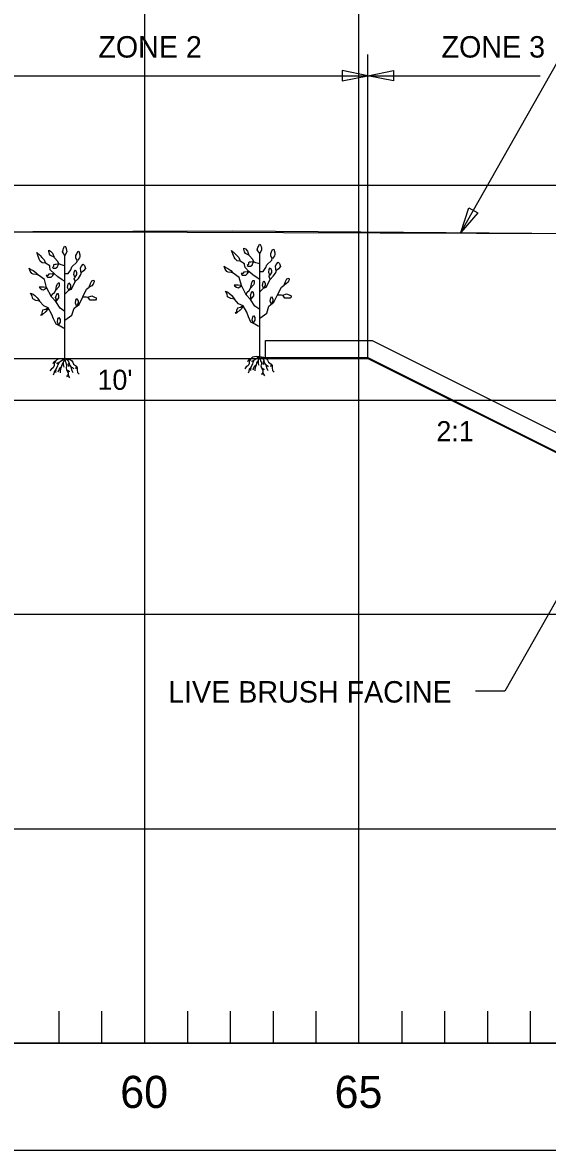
# Model space of a CAD drawing. Extents: x 1578769 to 1579225, y 724002 to 724828.
# Drawn here: x 1578861.35 to 1578873.59, y 724300.65 to 724326.95 of the extents above; entities that cross this region are included whole.
import ezdxf

# ---------------------------------------------------------------- set-up
doc = ezdxf.new("R2010")
doc.units = 0
for name, color, linetype in [('1', 7, 'Continuous'), ('Default', 7, 'Continuous'), ('Old_Level_1', 7, 'Continuous'), ('Old_Level_41', 7, 'Continuous'), ('Old_Level_42', 7, 'Continuous'), ('R_Exist Surface', 7, 'Continuous'), ('R_Fin Surface', 7, 'Continuous')]:
    doc.layers.add(name, color=color, linetype=linetype)

msp = doc.modelspace()

# ---------------------------------------------------------------- linework, layer by layer
at = {"layer": '1'}
for p, q in [((1578869.405, 724319.118), (1578869.405, 724326.205)), ((1578859.405, 724325.713), (1578869.405, 724325.713)), ((1578869.405, 724325.713), (1578873.428, 724325.713)), ((1578862.337, 724319.118), (1578862.337, 724321.518)), ((1578866.883, 724319.166), (1578866.883, 724321.566)), ((1578862.342, 724319.113), (1578862.344, 724319.117)), ((1578866.888, 724319.161), (1578866.89, 724319.165))]:
    msp.add_line(p, q, dxfattribs=at)
for points in [[(1578871.571, 724322.055), (1578874.669, 724327.519), (1578875.354, 724327.519)], [(1578862.624, 724321.405), (1578862.593, 724321.462), (1578862.593, 724321.518), (1578862.612, 724321.563), (1578862.637, 724321.613), (1578862.662, 724321.619), (1578862.688, 724321.537), (1578862.688, 724321.499), (1578862.681, 724321.468), (1578862.631, 724321.405)], [(1578867.17, 724321.452), (1578867.139, 724321.509), (1578867.139, 724321.566), (1578867.158, 724321.61), (1578867.183, 724321.661), (1578867.208, 724321.667), (1578867.233, 724321.585), (1578867.233, 724321.547), (1578867.227, 724321.516), (1578867.177, 724321.452)], [(1578862.325, 724320.925), (1578862.274, 724320.95), (1578862.173, 724321.026), (1578862.085, 724321.102), (1578861.997, 724321.19), (1578861.984, 724321.266), (1578861.984, 724321.278), (1578861.883, 724321.342)], [(1578862.337, 724321.278), (1578862.249, 724321.304), (1578862.199, 724321.329), (1578862.173, 724321.379), (1578862.098, 724321.468), (1578862.085, 724321.48)], [(1578862.337, 724321.102), (1578862.413, 724321.102), (1578862.476, 724321.19), (1578862.501, 724321.253), (1578862.615, 724321.367), (1578862.628, 724321.405)], [(1578862.716, 724321.102), (1578862.703, 724321.222), (1578862.716, 724321.266), (1578862.767, 724321.316), (1578862.798, 724321.285), (1578862.817, 724321.215), (1578862.773, 724321.165), (1578862.716, 724321.114)], [(1578866.871, 724320.972), (1578866.82, 724320.998), (1578866.719, 724321.073), (1578866.631, 724321.149), (1578866.542, 724321.238), (1578866.53, 724321.313), (1578866.53, 724321.326), (1578866.429, 724321.389)], [(1578866.883, 724321.326), (1578866.795, 724321.351), (1578866.744, 724321.377), (1578866.719, 724321.427), (1578866.643, 724321.516), (1578866.631, 724321.528)], [(1578866.883, 724321.149), (1578866.959, 724321.149), (1578867.022, 724321.238), (1578867.047, 724321.301), (1578867.161, 724321.415), (1578867.173, 724321.452)], [(1578867.262, 724321.149), (1578867.249, 724321.269), (1578867.262, 724321.313), (1578867.312, 724321.364), (1578867.344, 724321.332), (1578867.363, 724321.263), (1578867.319, 724321.212), (1578867.262, 724321.162)], [(1578861.719, 724321.064), (1578861.675, 724321.076), (1578861.599, 724321.083), (1578861.567, 724321.102), (1578861.53, 724321.158), (1578861.504, 724321.222), (1578861.504, 724321.228), (1578861.542, 724321.196), (1578861.593, 724321.171), (1578861.662, 724321.127), (1578861.719, 724321.064)], [(1578862.337, 724320.217), (1578862.224, 724320.293), (1578862.123, 724320.445), (1578862.022, 724320.558), (1578861.908, 724320.773), (1578861.858, 724320.963), (1578861.719, 724321.064)], [(1578862.337, 724320.634), (1578862.35, 724320.634), (1578862.426, 724320.71), (1578862.489, 724320.735), (1578862.577, 724320.912), (1578862.653, 724320.988), (1578862.703, 724321.064), (1578862.716, 724321.102)], [(1578862.571, 724321.013), (1578862.546, 724321.076), (1578862.558, 724321.152), (1578862.577, 724321.184), (1578862.609, 724321.133), (1578862.609, 724321.076), (1578862.571, 724321.013)], [(1578866.265, 724321.111), (1578866.221, 724321.124), (1578866.145, 724321.13), (1578866.113, 724321.149), (1578866.075, 724321.206), (1578866.05, 724321.269), (1578866.05, 724321.276), (1578866.088, 724321.244), (1578866.138, 724321.219), (1578866.208, 724321.175), (1578866.265, 724321.111)], [(1578866.883, 724320.265), (1578866.77, 724320.341), (1578866.669, 724320.492), (1578866.568, 724320.606), (1578866.454, 724320.821), (1578866.403, 724321.01), (1578866.265, 724321.111)], [(1578866.883, 724320.682), (1578866.896, 724320.682), (1578866.971, 724320.758), (1578867.035, 724320.783), (1578867.123, 724320.96), (1578867.199, 724321.036), (1578867.249, 724321.111), (1578867.262, 724321.149)], [(1578867.117, 724321.061), (1578867.091, 724321.124), (1578867.104, 724321.2), (1578867.123, 724321.231), (1578867.155, 724321.181), (1578867.155, 724321.124), (1578867.117, 724321.061)], [(1578867.123, 724320.96), (1578867.117, 724320.998), (1578867.098, 724321.023), (1578867.117, 724321.061)], [(1578861.908, 724320.773), (1578861.834, 724320.779), (1578861.777, 724320.779), (1578861.739, 724320.779), (1578861.758, 724320.76), (1578861.796, 724320.732), (1578861.834, 724320.722), (1578861.91, 724320.77)], [(1578862.337, 724320.01), (1578862.501, 724320.129), (1578862.552, 724320.293), (1578862.666, 724320.382), (1578862.754, 724320.558), (1578862.842, 724320.735), (1578862.905, 724320.786)], [(1578862.426, 724320.71), (1578862.4, 724320.773), (1578862.413, 724320.849), (1578862.432, 724320.88), (1578862.464, 724320.83), (1578862.464, 724320.773), (1578862.426, 724320.71)], [(1578862.577, 724320.912), (1578862.571, 724320.95), (1578862.552, 724320.975), (1578862.571, 724321.013)], [(1578862.905, 724320.786), (1578862.937, 724320.868), (1578862.969, 724320.931), (1578863.013, 724320.944), (1578863.019, 724320.912), (1578863, 724320.855), (1578862.962, 724320.817), (1578862.905, 724320.786)], [(1578866.454, 724320.821), (1578866.38, 724320.827), (1578866.322, 724320.827), (1578866.284, 724320.827), (1578866.303, 724320.808), (1578866.342, 724320.779), (1578866.38, 724320.77), (1578866.456, 724320.817)], [(1578866.883, 724320.057), (1578867.047, 724320.177), (1578867.098, 724320.341), (1578867.211, 724320.429), (1578867.3, 724320.606), (1578867.388, 724320.783), (1578867.451, 724320.833)], [(1578866.971, 724320.758), (1578866.946, 724320.821), (1578866.959, 724320.897), (1578866.978, 724320.928), (1578867.009, 724320.878), (1578867.009, 724320.821), (1578866.971, 724320.758)], [(1578867.451, 724320.833), (1578867.483, 724320.916), (1578867.514, 724320.979), (1578867.558, 724320.991), (1578867.565, 724320.96), (1578867.546, 724320.903), (1578867.508, 724320.865), (1578867.451, 724320.833)], [(1578862.022, 724320.558), (1578862.041, 724320.622), (1578862.091, 724320.659), (1578862.123, 724320.71)], [(1578862.754, 724320.558), (1578862.817, 724320.558), (1578862.842, 724320.558), (1578862.874, 724320.546)], [(1578862.874, 724320.546), (1578862.962, 724320.577), (1578863.025, 724320.552), (1578863.069, 724320.533), (1578863.069, 724320.502), (1578863.051, 724320.483), (1578863.019, 724320.476), (1578862.975, 724320.483), (1578862.924, 724320.483), (1578862.874, 724320.546)], [(1578866.568, 724320.606), (1578866.587, 724320.669), (1578866.637, 724320.707), (1578866.669, 724320.758)], [(1578867.152, 724320.392), (1578867.127, 724320.455), (1578867.14, 724320.531), (1578867.159, 724320.563), (1578867.19, 724320.512), (1578867.19, 724320.455), (1578867.152, 724320.392)], [(1578867.3, 724320.606), (1578867.363, 724320.606), (1578867.388, 724320.606), (1578867.42, 724320.594)], [(1578867.42, 724320.594), (1578867.508, 724320.625), (1578867.571, 724320.6), (1578867.615, 724320.581), (1578867.615, 724320.549), (1578867.596, 724320.53), (1578867.565, 724320.524), (1578867.521, 724320.53), (1578867.47, 724320.53), (1578867.42, 724320.594)], [(1578862.34, 724319.814), (1578862.302, 724319.824), (1578862.225, 724319.872), (1578862.13, 724319.919), (1578862.073, 724320.044), (1578862.034, 724320.149), (1578861.949, 724320.302), (1578861.844, 724320.349), (1578861.748, 724320.454), (1578861.748, 724320.454)], [(1578862.607, 724320.344), (1578862.581, 724320.408), (1578862.594, 724320.483), (1578862.613, 724320.515), (1578862.645, 724320.464), (1578862.645, 724320.408), (1578862.607, 724320.344)], [(1578866.886, 724319.862), (1578866.848, 724319.872), (1578866.771, 724319.919), (1578866.676, 724319.967), (1578866.618, 724320.091), (1578866.58, 724320.196), (1578866.494, 724320.349), (1578866.389, 724320.397), (1578866.294, 724320.502), (1578866.294, 724320.502)], [(1578862.187, 724319.905), (1578862.161, 724319.968), (1578862.174, 724320.044), (1578862.193, 724320.075), (1578862.225, 724320.025), (1578862.225, 724319.968), (1578862.187, 724319.905)], [(1578866.732, 724319.953), (1578866.707, 724320.016), (1578866.72, 724320.092), (1578866.739, 724320.123), (1578866.77, 724320.073), (1578866.77, 724320.016), (1578866.732, 724319.953)], [(1578862.337, 724319.118), (1578862.286, 724319.113), (1578862.27, 724319.117), (1578862.212, 724319.109), (1578862.177, 724319.101), (1578862.15, 724319.085), (1578862.119, 724319.054), (1578862.096, 724319.019), (1578862.088, 724318.985), (1578862.088, 724318.953), (1578862.073, 724318.918), (1578862.061, 724318.903), (1578862.022, 724318.876), (1578861.987, 724318.829)], [(1578862.119, 724319.054), (1578862.076, 724319.035), (1578862.061, 724319.012), (1578862.049, 724319.004)], [(1578862.337, 724319.118), (1578862.27, 724319.07), (1578862.232, 724319.051), (1578862.193, 724319.019), (1578862.173, 724318.981), (1578862.166, 724318.95), (1578862.127, 724318.864), (1578862.092, 724318.821), (1578862.08, 724318.771), (1578862.065, 724318.728)], [(1578862.193, 724319.019), (1578862.15, 724319.012), (1578862.146, 724318.996)], [(1578862.337, 724319.118), (1578862.298, 724319.023), (1578862.263, 724318.969), (1578862.251, 724318.918), (1578862.235, 724318.88), (1578862.224, 724318.821), (1578862.224, 724318.783)], [(1578862.298, 724319.023), (1578862.298, 724318.969), (1578862.301, 724318.946), (1578862.313, 724318.915)], [(1578862.337, 724319.118), (1578862.421, 724319.102), (1578862.464, 724319.089), (1578862.492, 724319.07), (1578862.519, 724319.031), (1578862.538, 724318.985), (1578862.604, 724318.938), (1578862.627, 724318.911), (1578862.627, 724318.852), (1578862.631, 724318.794), (1578862.67, 724318.755)], [(1578862.337, 724319.118), (1578862.406, 724319.082), (1578862.43, 724319.027), (1578862.441, 724318.973), (1578862.476, 724318.926), (1578862.499, 724318.841), (1578862.523, 724318.79)], [(1578862.337, 724319.118), (1578862.344, 724319.054), (1578862.356, 724319.027), (1578862.367, 724318.988), (1578862.375, 724318.973), (1578862.375, 724318.942), (1578862.364, 724318.903), (1578862.375, 724318.856), (1578862.391, 724318.821), (1578862.41, 724318.783), (1578862.41, 724318.748), (1578862.422, 724318.705), (1578862.445, 724318.67)], [(1578862.43, 724319.027), (1578862.418, 724318.996), (1578862.406, 724318.981), (1578862.426, 724318.934)], [(1578862.604, 724318.938), (1578862.592, 724318.899), (1578862.589, 724318.88)], [(1578866.883, 724319.166), (1578866.832, 724319.16), (1578866.816, 724319.164), (1578866.758, 724319.156), (1578866.723, 724319.149), (1578866.696, 724319.133), (1578866.665, 724319.102), (1578866.642, 724319.067), (1578866.634, 724319.032), (1578866.634, 724319.001), (1578866.618, 724318.966), (1578866.607, 724318.951), (1578866.568, 724318.923), (1578866.533, 724318.877)], [(1578866.665, 724319.102), (1578866.622, 724319.083), (1578866.607, 724319.059), (1578866.595, 724319.052)], [(1578866.883, 724319.166), (1578866.816, 724319.118), (1578866.777, 724319.098), (1578866.739, 724319.067), (1578866.719, 724319.028), (1578866.711, 724318.997), (1578866.673, 724318.912), (1578866.638, 724318.869), (1578866.626, 724318.819), (1578866.611, 724318.776)], [(1578866.739, 724319.067), (1578866.696, 724319.059), (1578866.692, 724319.044)], [(1578866.797, 724318.966), (1578866.75, 724318.927), (1578866.746, 724318.908), (1578866.739, 724318.904), (1578866.719, 724318.846)], [(1578866.883, 724319.166), (1578866.843, 724319.071), (1578866.808, 724319.017), (1578866.797, 724318.966), (1578866.781, 724318.927), (1578866.77, 724318.869), (1578866.77, 724318.83)], [(1578866.843, 724319.071), (1578866.843, 724319.017), (1578866.847, 724318.993), (1578866.859, 724318.962)], [(1578866.883, 724319.166), (1578866.967, 724319.15), (1578867.01, 724319.137), (1578867.037, 724319.118), (1578867.064, 724319.079), (1578867.084, 724319.032), (1578867.15, 724318.986), (1578867.173, 724318.958), (1578867.173, 724318.9), (1578867.177, 724318.842), (1578867.216, 724318.803)], [(1578866.883, 724319.166), (1578866.952, 724319.129), (1578866.975, 724319.075), (1578866.987, 724319.021), (1578867.022, 724318.974), (1578867.045, 724318.889), (1578867.068, 724318.838)], [(1578866.883, 724319.166), (1578866.89, 724319.102), (1578866.902, 724319.075), (1578866.913, 724319.036), (1578866.921, 724319.021), (1578866.921, 724318.99), (1578866.909, 724318.951), (1578866.921, 724318.904), (1578866.936, 724318.869), (1578866.956, 724318.83), (1578866.956, 724318.795), (1578866.967, 724318.753), (1578866.991, 724318.718)], [(1578866.975, 724319.075), (1578866.964, 724319.044), (1578866.952, 724319.028), (1578866.971, 724318.982)], [(1578867.022, 724318.974), (1578867.057, 724318.955), (1578867.076, 724318.943), (1578867.088, 724318.931)], [(1578867.15, 724318.986), (1578867.138, 724318.947), (1578867.134, 724318.927)], [(1578862.127, 724318.864), (1578862.119, 724318.81), (1578862.123, 724318.794)], [(1578862.251, 724318.918), (1578862.204, 724318.88), (1578862.201, 724318.86), (1578862.193, 724318.856), (1578862.173, 724318.798)], [(1578862.375, 724318.856), (1578862.41, 724318.841), (1578862.433, 724318.821), (1578862.437, 724318.806)], [(1578862.41, 724318.748), (1578862.383, 724318.713), (1578862.387, 724318.689)], [(1578862.476, 724318.926), (1578862.511, 724318.907), (1578862.53, 724318.895), (1578862.542, 724318.884)], [(1578866.673, 724318.912), (1578866.665, 724318.858), (1578866.669, 724318.842)], [(1578866.921, 724318.904), (1578866.956, 724318.889), (1578866.979, 724318.869), (1578866.983, 724318.854)], [(1578866.956, 724318.795), (1578866.929, 724318.76), (1578866.933, 724318.737)], [(1578874.817, 724315.267), (1578872.601, 724311.358), (1578871.916, 724311.358)]]:
    msp.add_lwpolyline(points, dxfattribs=at)
for points in [[(1578868.805, 724325.593), (1578869.405, 724325.713), (1578868.805, 724325.833)], [(1578870.005, 724325.593), (1578869.405, 724325.713), (1578870.005, 724325.833)], [(1578871.971, 724322.517), (1578871.571, 724322.055), (1578871.762, 724322.636)], [(1578861.883, 724321.342), (1578861.807, 724321.348), (1578861.763, 724321.392), (1578861.738, 724321.436), (1578861.694, 724321.55), (1578861.681, 724321.588), (1578861.757, 724321.518), (1578861.801, 724321.474), (1578861.851, 724321.424)], [(1578862.085, 724321.48), (1578862.003, 724321.518), (1578861.978, 724321.556), (1578861.965, 724321.619), (1578861.965, 724321.645), (1578862.003, 724321.626), (1578862.047, 724321.575)], [(1578862.337, 724321.518), (1578862.293, 724321.582), (1578862.281, 724321.607), (1578862.293, 724321.657), (1578862.306, 724321.683), (1578862.331, 724321.739), (1578862.35, 724321.733), (1578862.369, 724321.683), (1578862.375, 724321.645), (1578862.382, 724321.607)], [(1578866.429, 724321.389), (1578866.353, 724321.396), (1578866.309, 724321.44), (1578866.284, 724321.484), (1578866.239, 724321.598), (1578866.227, 724321.636), (1578866.303, 724321.566), (1578866.347, 724321.522), (1578866.397, 724321.471)], [(1578866.631, 724321.528), (1578866.549, 724321.566), (1578866.523, 724321.604), (1578866.511, 724321.667), (1578866.511, 724321.692), (1578866.549, 724321.673), (1578866.593, 724321.623)], [(1578866.883, 724321.566), (1578866.839, 724321.629), (1578866.826, 724321.655), (1578866.839, 724321.705), (1578866.852, 724321.73), (1578866.877, 724321.787), (1578866.896, 724321.781), (1578866.915, 724321.73), (1578866.921, 724321.692), (1578866.927, 724321.655)], [(1578862.199, 724321.329), (1578862.13, 724321.314), (1578862.101, 724321.314), (1578862.073, 724321.305), (1578862.073, 724321.266), (1578862.044, 724321.238), (1578862.063, 724321.228), (1578862.12, 724321.228), (1578862.159, 724321.247), (1578862.178, 724321.295)], [(1578866.744, 724321.377), (1578866.676, 724321.362), (1578866.647, 724321.362), (1578866.618, 724321.352), (1578866.618, 724321.314), (1578866.59, 724321.286), (1578866.609, 724321.276), (1578866.666, 724321.276), (1578866.704, 724321.295), (1578866.723, 724321.343)], [(1578862.085, 724321.102), (1578862.044, 724321.095), (1578861.987, 724321.085), (1578861.958, 724321.085), (1578861.949, 724321.056), (1578861.901, 724321.056), (1578861.929, 724321.018), (1578861.968, 724321.018), (1578862.015, 724321.018), (1578862.054, 724321.056)], [(1578866.631, 724321.149), (1578866.59, 724321.142), (1578866.533, 724321.133), (1578866.504, 724321.133), (1578866.494, 724321.104), (1578866.447, 724321.104), (1578866.475, 724321.066), (1578866.513, 724321.066), (1578866.561, 724321.066), (1578866.599, 724321.104)], [(1578862.123, 724320.71), (1578862.142, 724320.805), (1578862.154, 724320.843), (1578862.161, 724320.862), (1578862.186, 724320.887), (1578862.205, 724320.887), (1578862.205, 724320.817), (1578862.192, 724320.792)], [(1578866.669, 724320.758), (1578866.687, 724320.852), (1578866.7, 724320.89), (1578866.706, 724320.909), (1578866.732, 724320.935), (1578866.751, 724320.935), (1578866.751, 724320.865), (1578866.738, 724320.84)], [(1578861.748, 724320.454), (1578861.662, 724320.474), (1578861.586, 724320.512), (1578861.576, 724320.569), (1578861.538, 724320.646), (1578861.595, 724320.617), (1578861.634, 724320.588), (1578861.691, 724320.531), (1578861.719, 724320.493)], [(1578862.123, 724320.445), (1578862.13, 724320.521), (1578862.12, 724320.54), (1578862.139, 724320.598), (1578862.168, 724320.636), (1578862.178, 724320.636), (1578862.187, 724320.579), (1578862.187, 724320.531)], [(1578866.294, 724320.502), (1578866.208, 724320.521), (1578866.132, 724320.559), (1578866.122, 724320.617), (1578866.084, 724320.693), (1578866.141, 724320.665), (1578866.179, 724320.636), (1578866.237, 724320.579), (1578866.265, 724320.54)], [(1578866.669, 724320.492), (1578866.676, 724320.569), (1578866.666, 724320.588), (1578866.685, 724320.645), (1578866.714, 724320.684), (1578866.723, 724320.684), (1578866.733, 724320.626), (1578866.733, 724320.579)], [(1578861.949, 724320.302), (1578861.891, 724320.263), (1578861.815, 724320.244), (1578861.796, 724320.187), (1578861.796, 724320.149), (1578861.767, 724320.13), (1578861.805, 724320.139), (1578861.882, 724320.206), (1578861.891, 724320.206), (1578861.949, 724320.273)], [(1578866.494, 724320.349), (1578866.437, 724320.311), (1578866.361, 724320.292), (1578866.342, 724320.235), (1578866.342, 724320.196), (1578866.313, 724320.177), (1578866.351, 724320.187), (1578866.428, 724320.254), (1578866.437, 724320.254), (1578866.494, 724320.321)]]:
    msp.add_lwpolyline(points, close=True, dxfattribs=at)
at = {"layer": 'Default'}
msp.add_line((1578824.194, 724303.15), (1579224.194, 724303.15), dxfattribs=at)
msp.add_lwpolyline([(1578822.944, 724322.15), (1578824.354, 724322.105), (1578827.254, 724322.088), (1578831.424, 724322.063), (1578836.824, 724322.031), (1578858.594, 724322.068), (1578861.134, 724322.067), (1578862.944, 724322.071), (1578882.454, 724322.012), (1578884.524, 724320.413), (1578890.394, 724312.796), (1578905.444, 724309.389), (1578918.124, 724306.852), (1578923.764, 724306.998), (1578939.004, 724307.393), (1578947.244, 724307.607), (1578961.874, 724307.852), (1578966.594, 724307.868), (1579023.724, 724312.412), (1579059.084, 724315.375), (1579126.244, 724320.038), (1579145.794, 724321.276)], dxfattribs=at)
at = {"layer": 'Old_Level_1'}
for points in [[(1578819.194, 724335.65), (1578926.694, 724335.65), (1578926.694, 724300.65), (1578819.194, 724300.65)], [(1578824.194, 724333.15), (1578924.194, 724333.15), (1578924.194, 724303.15), (1578824.194, 724303.15)]]:
    msp.add_lwpolyline(points, close=True, dxfattribs=at)
at = {"layer": 'Old_Level_41'}
for p, q in [((1578864.194, 724333.15), (1578864.194, 724303.15)), ((1578869.194, 724303.15), (1578869.194, 724333.15))]:
    msp.add_line(p, q, dxfattribs=at)
for points in [[(1578924.194, 724323.15), (1578824.194, 724323.15)], [(1578824.194, 724318.15), (1578924.194, 724318.15)], [(1578924.194, 724313.15), (1578824.194, 724313.15)], [(1578824.194, 724308.15), (1578924.194, 724308.15)]]:
    msp.add_lwpolyline(points, dxfattribs=at)
at = {"layer": 'Old_Level_42'}
for p, q in [((1578862.194, 724303.9), (1578862.194, 724303.15)), ((1578863.194, 724303.9), (1578863.194, 724303.15)), ((1578865.194, 724303.9), (1578865.194, 724303.15)), ((1578866.194, 724303.9), (1578866.194, 724303.15)), ((1578867.194, 724303.9), (1578867.194, 724303.15)), ((1578868.194, 724303.9), (1578868.194, 724303.15)), ((1578870.194, 724303.9), (1578870.194, 724303.15)), ((1578871.194, 724303.9), (1578871.194, 724303.15)), ((1578872.194, 724303.9), (1578872.194, 724303.15)), ((1578873.194, 724303.9), (1578873.194, 724303.15))]:
    msp.add_line(p, q, dxfattribs=at)
at = {"layer": 'R_Exist Surface'}
msp.add_lwpolyline([(1578824.194, 724322.162), (1578829.284, 724322.091), (1578836.275, 724322.056), (1578841.243, 724322.049), (1578852.243, 724322.048), (1578866.252, 724322.093), (1578877.209, 724322.014), (1578882.216, 724322.036), (1578883.229, 724321.428), (1578884.216, 724320.636), (1578885.259, 724319.504), (1578887.377, 724316.691), (1578890.502, 724312.788), (1578895.252, 724311.694), (1578904.139, 724309.679), (1578908.201, 724308.813), (1578914.491, 724307.577), (1578918.186, 724306.844), (1578924.194, 724307.012)], dxfattribs=at)
at = {"layer": 'R_Fin Surface'}
for p, q in [((1578867.015, 724319.138), (1578867.015, 724319.538)), ((1578867.015, 724319.538), (1578869.504, 724319.538)), ((1578869.504, 724319.538), (1578875.555, 724316.513)), ((1578859.405, 724319.118), (1578869.405, 724319.118)), ((1578859.405, 724319.118), (1578869.405, 724319.118)), ((1578869.41, 724319.138), (1578867.015, 724319.138)), ((1578869.405, 724319.118), (1578875.455, 724316.093)), ((1578869.405, 724319.118), (1578875.455, 724316.093)), ((1578875.46, 724316.113), (1578869.41, 724319.138))]:
    msp.add_line(p, q, dxfattribs=at)

# ---------------------------------------------------------------- texts
at = {"layer": '1'}
for s, height, p in [('ZONE 2', 0.5, (1578863.117, 724326.137)), ('ZONE 3', 0.5, (1578871.124, 724326.137)), ("10'", 0.4687, (1578863.097, 724318.389)), ('2:1', 0.4687, (1578871.004, 724317.19)), ('LIVE BRUSH FACINE', 0.5, (1578864.746, 724311.095)), ('60', 0.75, (1578863.628, 724301.64)), ('65', 0.75, (1578868.628, 724301.64))]:
    msp.add_text(s, height=height, dxfattribs=at).set_placement(p)

doc.saveas('drawing.dxf')
